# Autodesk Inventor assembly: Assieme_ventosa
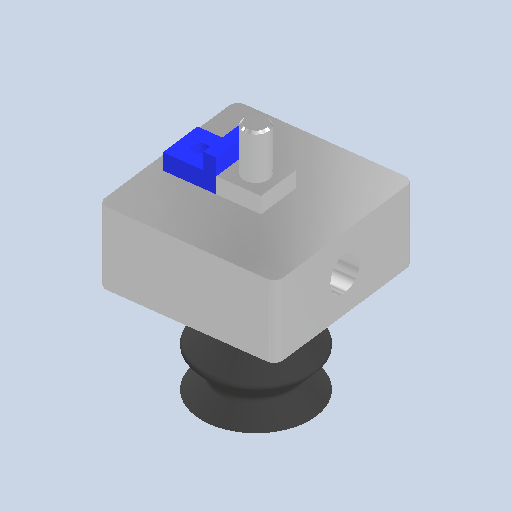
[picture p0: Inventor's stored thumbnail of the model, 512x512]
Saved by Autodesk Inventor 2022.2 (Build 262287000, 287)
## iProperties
Created: 2024-10
Part Number: Assieme_ventosa
Document SubType Name: Assembly
Designer: 18907419
Author: 18907419
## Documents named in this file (4)
- C:\Users\18907419\Desktop\automazione\smistamento\Assieme_ventosa.iam
- C:\Users\18907419\Desktop\automazione\smistamento\ventosa 27 mm.ipt
- C:\Users\18907419\Desktop\automazione\smistamento\piastra_ventosa.ipt
- C:\Users\18907419\Desktop\automazione\smistamento\blocco_ventosa_cilindro.ipt
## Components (3 placed, 3 different names)
1. ventosa 27 mm:1
2. piastra_ventosa:1
3. blocco_ventosa_cilindro:1
